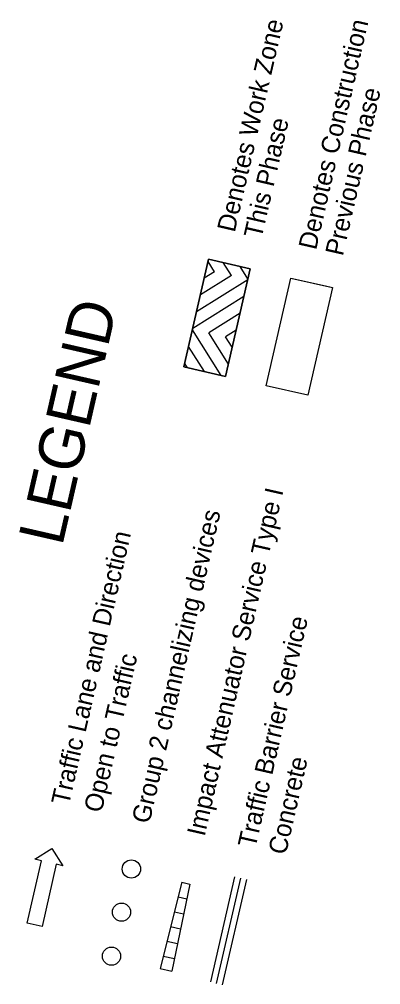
# Model space of a CAD drawing. Extents: x 1616334 to 1616452, y 901344 to 901662.
import ezdxf

# ---------------------------------------------------------------- set-up
doc = ezdxf.new("R2010")
doc.units = 0
for name, color, linetype in [('Default', 7, 'Continuous'), ('Gray Area Fill Shapes', 7, 'Continuous'), ('Stage 1', 7, 'Continuous')]:
    doc.layers.add(name, color=color, linetype=linetype)

msp = doc.modelspace()

# ---------------------------------------------------------------- linework, layer by layer
at = {"layer": 'Default'}
for p, q in [((1616414.64, 901541.19), (1616422.74, 901576.58)), ((1616422.74, 901576.58), (1616434.15, 901573.97)), ((1616436.37, 901573.46), (1616428.27, 901538.07)), ((1616434.15, 901573.97), (1616436.37, 901573.46)), ((1616428.27, 901538.07), (1616414.64, 901541.19)), ((1616338.78, 901385.64), (1616344.37, 901389.21)), ((1616344.37, 901389.21), (1616347.99, 901383.53)), ((1616336.29, 901364.67), (1616340.97, 901385.14)), ((1616340.97, 901385.14), (1616338.78, 901385.64)), ((1616345.8, 901384.04), (1616341.11, 901363.57)), ((1616347.99, 901383.53), (1616345.8, 901384.04)), ((1616386.99, 901378.11), (1616379.84, 901349.82)), ((1616389.58, 901377.52), (1616383.71, 901348.93)), ((1616386.99, 901378.11), (1616389.58, 901377.52)), ((1616386.99, 901378.11), (1616389.58, 901377.52)), ((1616404.26, 901379.93), (1616396.34, 901345.34)), ((1616406.21, 901379.49), (1616398.29, 901344.89)), ((1616408.16, 901379.04), (1616400.24, 901344.45)), ((1616385.77, 901373.26), (1616388.57, 901372.62)), ((1616384.54, 901368.42), (1616387.57, 901367.73)), ((1616341.11, 901363.57), (1616336.29, 901364.67)), ((1616383.31, 901363.57), (1616386.56, 901362.83)), ((1616382.09, 901358.72), (1616385.56, 901357.93)), ((1616380.86, 901353.87), (1616384.56, 901353.03)), ((1616379.84, 901349.82), (1616383.71, 901348.93))]:
    msp.add_line(p, q, dxfattribs=at)
for points in [[(1616387.67, 901547.36), (1616395.77, 901582.75), (1616409.41, 901579.63), (1616401.31, 901544.24)], [(1616414.64, 901541.19), (1616422.74, 901576.58), (1616436.37, 901573.46), (1616428.27, 901538.07)], [(1616414.64, 901541.19), (1616422.74, 901576.58), (1616436.37, 901573.46), (1616428.27, 901538.07)]]:
    msp.add_lwpolyline(points, close=True, dxfattribs=at)
for centre in [(1616370.43, 901382.45), (1616367.19, 901368.28), (1616363.9, 901353.82)]:
    msp.add_circle(centre, 3, dxfattribs=at)
at = {"layer": 'Gray Area Fill Shapes'}
msp.add_lwpolyline([(1616401.31, 901544.24), (1616409.41, 901579.63), (1616395.77, 901582.75), (1616387.67, 901547.36), (1616401.31, 901544.24)], dxfattribs=at)
at = {"layer": 'Stage 1'}
for p, q in [((1616397.71, 901578.65), (1616395.6, 901582.01)), ((1616403.22, 901577.39), (1616400.54, 901581.66)), ((1616408.64, 901576.29), (1616406.06, 901580.4)), ((1616403.22, 901577.39), (1616393.09, 901571.03)), ((1616397.71, 901578.65), (1616394.35, 901576.55)), ((1616408.58, 901576.03), (1616391.83, 901565.52)), ((1616407.32, 901570.52), (1616390.57, 901560)), ((1616406.06, 901565), (1616395.81, 901558.57)), ((1616399.87, 901544.57), (1616390.47, 901559.56)), ((1616402.24, 901548.32), (1616395.81, 901558.57)), ((1616404.79, 901559.49), (1616401.32, 901557.31)), ((1616403.5, 901553.84), (1616401.32, 901557.31)), ((1616394.36, 901545.83), (1616389.2, 901554.05)), ((1616388.84, 901547.09), (1616387.94, 901548.53))]:
    msp.add_line(p, q, dxfattribs=at)

# ---------------------------------------------------------------- texts
at = {"layer": 'Default'}
for s, height, rotation, p in [('Denotes Work Zone ', 6, 76.9614, (1616404.31, 901591.35)), ('Denotes Construction ', 6, 77.125, (1616431.01, 901585.57)), ('Previous Phase', 6, 77.125, (1616439.78, 901583.57)), ('This Phase', 6, 76.9614, (1616413.08, 901589.32)), ('LEGEND', 14.777, 77.1084, (1616347.71, 901488.23)), ('Impact Attenuator Service Type I ', 6, 77.1855, (1616394.45, 901392.93)), ('Group 2 channelizing devices', 6, 77.1504, (1616376.33, 901397.09)), ('Traffic Lane and Direction ', 6, 77.1504, (1616349.91, 901403.13)), ('Traffic Barrier Service ', 6, 77.125, (1616411.12, 901389.12)), ('Open to Traffic', 6, 77.1504, (1616360.63, 901400.69)), ('Concrete', 6, 77.125, (1616421.07, 901386.85))]:
    msp.add_text(s, height=height, rotation=rotation, dxfattribs=at).set_placement(p)

doc.saveas('drawing.dxf')
